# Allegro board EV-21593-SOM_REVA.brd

Outline 63.5 x 101.6 mm; copper layers: TOP, L2_PWR, L3_GND, L4_SIG, L5_SIG, L6_GND, L7_PWR, BOTTOM. Coordinates in mm from the lower left corner of the outline.
Outline path: 0,101.6 0,0 63.5,0 63.5,101.6 0,101.6

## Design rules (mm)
constraint set DEFAULT: min track width 0.076
net group 90_OHM_E: nets $9N2153 $9N2154
net group ADD_CNTRL_E: nets DMC0_A00 DMC0_A01 DMC0_A02 DMC0_A03 DMC0_A04 DMC0_A05 DMC0_A06 DMC0_A07 DMC0_A08 DMC0_A09 DMC0_A10 DMC0_A11 DMC0_A12 DMC0_A13 DMC0_A14 DMC0_A15 DMC0_BA0 DMC0_BA1 DMC0_BA2 DMC0_CKE DMC0_ODT ~DMC0_CAS ~DMC0_CS0 ~DMC0_RAS ~DMC0_WE
net group CLOCK_E: nets $5N38 AUDIO_CLK DAI0_PIN01 DAI0_PIN02 DAI0_PIN04 PA_04/SPI2_CLK/OSPI_CLK/SMC0_D04 PC_07/LP1_CLK/OSPI_SEL4B/TM0_TMR9/SYS_FAULT SYS_CLKIN0 SYS_CLKOUT
net group DDR_LOWER_E: nets DMC0_DQ00 DMC0_DQ01 DMC0_DQ02 DMC0_DQ03 DMC0_DQ04 DMC0_DQ05 DMC0_DQ06 DMC0_DQ07 DMC0_LDM
net group DDR_UPPER_E: nets DMC0_DQ08 DMC0_DQ09 DMC0_DQ10 DMC0_DQ11 DMC0_DQ12 DMC0_DQ13 DMC0_DQ14 DMC0_DQ15 DMC0_UDM
net group PWR/GND_E: nets 1_8V 1_35V 1V2 2V7 3V 3V3OUT_FT232RQ $6N3598 $6N5877 $8N2576 $8N2617 $8N3809 $8N3812 $9N2124 $9N2155 $12N6006 $12N7788 $12N7803 $12N7837 $12N8016 $12N8049 $12N8051 $12N8425 $12N8479 $13N133 $13N256 $13N259 $13N306 $13N308 $13N309 $13N457 $13N525 $13N528 $13N593 $13N599 $13N626 CC1 CC2 DMC0_VREF GND INTVCC PG1 PG3 PG4 USB_SHELL USB_VBUS VBUS_TYPEC VDD_CONNECTOR VDD_EXT VDD_INPUT VDD_INT VDD_PLL VDD_VREF_EXT VTT

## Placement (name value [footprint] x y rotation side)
C1  .10  [CAPC0603X33N]  44.7 81.92 180 bottom
C2  .10  [CAPC2012X135N]  54.61 77.34 180 top
C3  .10  [CAPC2012X135N]  54.61 75.18 180 top
C4  .10  [CAPC2012X135N]  59.69 72.64 0 top
C5  .10  [CAPC2012X135N]  59.64 67.79 0 top
C6  .10  [CAPC2012X135N]  59.64 70.19 0 top
C7  .10  [CAPC1005X55N]  55.24 68.58 270 top
C8  .10  [CAPC1608X55N]  52.44 67.99 270 top
C9  .10  [CAPC1005X56N]  49.91 72.01 0 top
C10  .10  [CAPC1005X55N]  47.42 56.54 0 bottom
C11  .10  [CAPC1005X56N]  32.22 70.74 90 top
C12  .10  [CAPC1005X56N]  41.62 77.74 0 top
C13  .10  [CAPC1005X56N]  41.62 76.14 0 top
C14  .10  [CAPC1005X56N]  41.62 74.54 0 top
C15  .10  [CAPC1005X56N]  41.62 71.34 0 top
C16  .10  [CAPC1005X56N]  41.62 72.94 0 top
C17  .10  [CAPC3225X270N]  54.23 80.9 90 top
C18  .10  [CAPC3225X270N]  47.62 66.04 270 bottom
C19  .10  [CAPC3216X180N]  40.64 85.09 270 bottom
C20  .10  [CAPC3216X180N]  50.67 66.04 270 bottom
C21  .10  [CAPC1005X55N]  32.22 81.94 90 top
C22  .10  [CAPC1005X55N]  37.82 81.94 90 top
C23  .10  [CAPC1005X55N]  29.82 81.94 90 top
C24  .10  [CAPC1005X55N]  28.22 70.74 270 top
C25  .10  [CAPC1005X55N]  30.62 70.74 270 top
C26  .10  [CAPC1005X55N]  37.82 70.74 270 top
C27  .10  [CAPC1005X55N]  28.22 81.94 90 top
C28  .10  [CAPC1005X56N]  48.64 58.17 90 top
C29  .10  [CAPC1608X90N]  46.99 58.42 90 top
C30  .10  [CAPC1005X56N]  48.64 53.72 90 top
C31  .10  [CAPC1608X90N]  46.99 54.1 90 top
C32  .10  [CAPC1005X55N]  29.92 53.64 0 bottom
C33  .10  [CAPC1005X55N]  19.62 56.14 90 bottom
C34  .10  [CAPC0603X33N]  35.18 85.85 270 bottom
C35  .10  [CAPC0603X33N]  42.55 65.66 270 bottom
C36  .10  [CAPC1005X56N]  21.84 46.61 180 top
C37  .10  [CAPC1005X56N]  47.42 48.54 0 top
C38  .10  [CAPC1005X56N]  44.22 50.14 0 top
C39  .10  [CAPC2012X135N]  47.22 42.14 270 bottom
C40  .10  [CAPC2012X135N]  18.62 42.14 270 bottom
C41  .10  [CAPC2012X135N]  17.82 52.94 180 bottom
C42  .10  [CAPC2012X135N]  17.82 50.54 180 bottom
C43  .10  [CAPC2012X135N]  18.62 45.94 90 bottom
C44  .10  [CAPC2012X135N]  50.42 47.34 270 bottom
C45  .10  [CAPC1005X55N]  22.62 42.14 270 bottom
C46  .10  [CAPC1005X55N]  44.22 45.34 0 top
C47  .10  [CAPC1005X55N]  47.42 50.14 0 top
C48  .10  [CAPC1005X55N]  47.42 46.94 0 top
C49  .10  [CAPC1005X55N]  47.42 51.74 0 top
C50  .10  [CAPC1005X55N]  44.22 48.54 0 top
C51  .10  [CAPC1005X55N]  47.42 45.34 0 top
C52  .10  [CAPC1005X55N]  21.82 55.34 180 top
C53  .10  [CAPC1005X55N]  21.82 54.14 180 top
C54  .10  [CAPC1005X55N]  21.82 52.94 180 top
C55  .10  [CAPC1005X55N]  21.82 49.14 180 top
C56  .10  [CAPC1005X55N]  38.22 53.34 0 bottom
C57  .10  [CAPC1005X50N]  21.82 58.14 180 top
C58  .10  [CAPC1005X50N]  27.82 55.74 180 bottom
C59  .10  [CAPC1005X50N]  35.42 53.34 180 bottom
C60  .10  [CAPC1005X50N]  38.62 58.34 90 bottom
C61  .10  [CAPC1005X50N]  27.42 53.34 180 bottom
C62  .10  [CAPC1005X50N]  21.82 56.74 180 top
C63  .10  [CAPC1005X50N]  21.82 61.34 180 top
C64  .10  [CAPC1005X50N]  21.82 56.74 180 bottom
C65  .10  [CAPC1005X50N]  21.82 52.94 180 bottom
C66  .10  [CAPC1005X50N]  21.82 59.74 180 bottom
C67  .10  [CAPC1005X50N]  21.82 47.94 180 bottom
C68  .10  [CAPC1005X50N]  21.82 61.34 180 bottom
C69  .10  [CAPC1005X50N]  21.82 49.14 180 bottom
C70  .10  [CAPC1005X50N]  21.82 50.54 180 top
C71  .10  [CAPC1005X50N]  21.82 58.14 180 bottom
C72  .10  [CAPC1005X50N]  28.02 49.44 0 bottom
C73  .10  [CAPC1005X50N]  30.62 42.14 270 bottom
C74  .10  [CAPC1005X50N]  25.82 42.14 270 bottom
C75  .10  [CAPC1005X50N]  21.02 42.14 270 bottom
C76  .10  [CAPC1005X50N]  43.42 42.14 270 bottom
C77  .10  [CAPC1005X50N]  45.02 42.14 270 bottom
C78  .10  [CAPC1005X50N]  42.02 42.14 270 bottom
C79  .10  [CAPC1005X50N]  39.02 50.94 0 bottom
C80  .10  [CAPC1005X50N]  29.02 42.14 270 bottom
C81  .10  [CAPC1005X50N]  24.22 42.14 270 bottom
C82  .10  [CAPC1005X50N]  29.02 42.14 270 top
C83  .10  [CAPC1005X50N]  32.22 42.14 270 top
C84  .10  [CAPC1005X50N]  35.42 42.14 270 bottom
C85  .10  [CAPC1005X50N]  27.42 42.14 270 bottom
C86  .10  [CAPC1005X50N]  32.22 42.14 270 bottom
C87  .10  [CAPC1005X50N]  33.82 42.14 270 bottom
C88  .10  [CAPC1005X50N]  33.82 42.14 270 top
C89  .10  [CAPC1005X55N]  44.22 58.14 0 bottom
C90  .10  [CAPC1005X55N]  44.22 64.54 0 bottom
C91  .10  [CAPC1005X55N]  35.42 55.34 270 bottom
C92  .10  [CAPC1005X55N]  30.62 55.34 270 bottom
C93  .10  [CAPC1005X55N]  44.22 61.34 0 top
C94  .10  [CAPC1005X55N]  44.22 59.74 0 top
C95  .10  [CAPC1005X55N]  35.42 64.34 90 bottom
C96  .10  [CAPC1005X55N]  44.22 62.94 0 top
C97  .10  [CAPC1005X55N]  33.42 56.54 180 bottom
C98  .10  [CAPC1005X50N]  32.22 64.34 90 top
C99  .10  [CAPC1005X50N]  47.42 61.34 0 bottom
C100  .10  [CAPC1005X50N]  47.42 62.94 0 top
C101  .10  [CAPC1005X50N]  33.82 64.34 90 top
C102  .10  [CAPC1005X50N]  38.62 64.34 90 bottom
C103  .10  [CAPC1005X50N]  35.42 64.34 90 top
C104  .10  [CAPC1005X50N]  44.22 58.14 0 top
C105  .10  [CAPC1005X50N]  37.02 64.34 90 top
C106  .10  [CAPC1005X50N]  38.62 64.34 90 top
C107  .10  [CAPC1005X50N]  47.42 62.94 0 bottom
C108  .10  [CAPC1005X50N]  47.42 61.34 0 top
C109  .10  [CAPC1005X50N]  32.22 64.34 90 bottom
C110  .10  [CAPC1005X50N]  33.82 64.34 90 bottom
C111  .10  [CAPC1005X55N]  21.82 64.14 90 bottom
C112  .10  [CAPC1005X55N]  44.22 59.74 0 bottom
C113  .10  [CAPC1005X55N]  21.82 54.14 180 bottom
C114  .10  [CAPC1005X55N]  21.82 55.34 180 bottom
C115  .10  [CAPC1005X55N]  21.82 51.74 180 bottom
C116  .10  [CAPC1005X55N]  21.82 50.54 180 bottom
C117  .10  [CAPC1005X56N]  44.22 61.34 0 bottom
C118  .10  [CAPC1005X56N]  44.22 62.94 0 bottom
C119  .10  [CAPC1005X56N]  37.02 64.34 90 bottom
C120  .10  [CAPC0603X33N]  33.82 50.94 90 bottom
C121  .10  [CAPC0603X33N]  31.42 50.94 90 bottom
C122  .10  [CAPC0603X33N]  30.02 52.54 0 bottom
C123  .10  [CAPC0603X33N]  32.22 50.94 90 bottom
C124  .10  [CAPC0603X33N]  43.42 42.14 270 top
C125  .10  [CAPC0603X33N]  35.42 42.14 270 top
C126  .10  [CAPC0603X33N]  42.02 42.14 270 top
C127  .10  [CAPC0603X33N]  45.02 42.14 270 top
C128  .10  [CAPC0603X33N]  21.02 42.14 270 top
C129  .10  [CAPC0603X33N]  25.82 42.14 270 top
C130  .10  [CAPC0603X33N]  34.62 50.94 90 bottom
C131  .10  [CAPC0603X33N]  30.62 50.94 90 bottom
C132  .10  [CAPC0603X33N]  47.42 51.74 0 bottom
C133  .10  [CAPC0603X33N]  44.22 45.34 0 bottom
C134  .10  [CAPC0603X33N]  47.42 46.94 0 bottom
C135  .10  [CAPC0603X33N]  47.42 50.14 0 bottom
C136  .10  [CAPC0603X33N]  44.22 50.14 0 bottom
C137  .10  [CAPC0603X33N]  21.84 45.34 180 bottom
C138  .10  [CAPC0603X33N]  44.22 46.94 0 bottom
C139  .10  [CAPC0603X33N]  47.42 45.34 0 bottom
C140  .10  [CAPC0603X33N]  21.84 46.61 180 bottom
C141  .10  [CAPC1005X55N]  9.53 56.52 180 top
C142  .10  [CAPC1005X55N]  9.53 45.09 180 top
C143  .10  [CAPC1005X55N]  46.99 32.38 270 bottom
C144  .10  [CAPC1005X55N]  46.99 34.92 90 bottom
C145  .10  [CAPC1005X55N]  43.18 34.92 270 bottom
C146  .10  [CAPC1005X56N]  17.72 63.88 90 bottom
C147  .10  [CAPC1005X56N]  58.42 32.38 180 top
C148  .10  [CAPC1005X56N]  58.42 41.27 180 top
C149  .10  [CAPC1005X56N]  58.42 27.3 180 top
C150  .10  [CAPC2012X135N]  53.85 59.18 270 top
C151  .10  [CAPC1005X55N]  45.47 12.06 90 top
C152  .10  [CAPC2012X140N]  28.19 26.16 180 bottom
C153  .10  [CAPC3216X180N]  50.29 15.62 90 top
C154  .10  [CAPC3216X180N]  60.96 63.5 90 top
C155  .10  [CAPC3225X280N]  11.43 22.73 90 top
C156  .10  [CAPC0603X33N]  47.12 15.88 90 top
C157  .10  [CAPC0603X33N]  42.93 15.49 90 top
C158  .10  [CAPC3216X127N]  21.34 16.89 270 top
C159  .10  [CAPC3225X280N]  24.38 16.89 270 top
C160  .10  [CAPC3216X127N]  14.22 16.89 270 top
C161  .10  [CAPC3225X280N]  11.3 16.89 270 top
C162  .10  [CAPC1608X87N]  17.78 19.05 180 top
C163  .10  [CAPC1005X55N]  17.78 10.79 90 top
C164  .10  [CAPC3225X280N]  22.23 21.72 0 top
C165  .10  [CAPC3225X280N]  22.23 25.02 0 top
C166  .10  [CAPC3225X280N]  22.23 28.32 0 top
C167  .10  [CAPC3216X127N]  22.73 12.06 90 top
C168  .10  [CAPC1005X55N]  16.51 10.79 270 top
C169  .10  [CAPC1005X50N]  29.34 18.67 90 top
C170  .10  [CAPC1005X50N]  34.92 18.41 270 top
C171  .10  [CAPC3216X180N]  36.83 19.18 270 top
C172  .10  [CAPC3216X180N]  27.43 19.43 90 top
C173  .10  [CAPC1005X55N]  27.81 13.08 90 top
C174  .10  [CAPC1608X90N]  31.12 12.57 90 top
C175  .10  [CAPC3216X180N]  40.64 15.62 90 top
C176  .10  [CAPC1005X56N]  48.01 9.91 90 top
C177  .10  [CAPC1005X55N]  33.15 28.45 90 top
C178  .10  [CAPC1608X90N]  33.02 12.57 90 top
C179  .10  [CAPC3225X280N]  27.56 23.49 180 top
C180  .10  [CAPC3225X280N]  27.56 26.8 180 top
C181  .10  [CAPC3225X280N]  36.7 23.49 0 top
C182  .10  [CAPC3225X280N]  27.56 23.49 180 bottom
C183  .10  [CAPC3225X280N]  36.7 23.49 0 bottom
C184  .10  [CAPC3225X280N]  36.7 26.8 0 top
C185  .10  [CAPC1005X50N]  29.21 13.08 90 top
C186  .10  [CAPC1005X56N]  22.23 38.73 90 bottom
C187  .10  [CAPC1005X56N]  17.15 34.92 270 bottom
C188  .10  [CAPC1005X56N]  17.15 38.73 270 bottom
C189  .10  [CAPC1005X56N]  17.15 31.12 270 bottom
C190  .10  [CAPC1005X56N]  16 79.25 90 bottom
C191  .10  [CAPC1005X55N]  19.69 93.34 270 bottom
C192  .10  [CAPC1005X55N]  7.62 98.43 90 bottom
C193  .10  [CAPC1005X55N]  13.46 87.12 0 bottom
C194  .10  [CAPC1608X90N]  10.29 87.12 180 bottom
C195  .10  [CAPC1005X55N]  19.81 82.93 270 bottom
C196  .10  [CAPC1005X55N]  18.54 82.93 270 bottom
C197  .10  [CAPC0603X33N]  47.42 48.54 0 bottom
C198  .10  [CAPC0603X33N]  44.22 48.54 0 bottom
C199  .10  [CAPC0603X33N]  21.82 45.34 180 top
C200  .10  [CAPC0603X33N]  30.62 42.14 270 top
C201  .10  [CAPC0603X33N]  44.7 72.01 180 bottom
C202  .10  [CAPC0603X33N]  44.7 78.49 180 bottom
C203  .10  [CAPC0603X33N]  44.7 75.31 180 bottom
C204  .10  [CAPC0603X33N]  38.8 85.85 270 bottom
C205  .10  [CAPC0603X33N]  41.53 65.66 270 bottom
C206  .10  [CAPC0603X33N]  33.27 87.76 180 bottom
C207  .10  [CAPC0603X33N]  33.27 86.74 180 bottom
C208  .10  [CAPC3216X180N]  26.67 91.44 180 top
C209  .10  [CAPC2012X145N]  44.58 98.43 270 bottom
C210  .10  [CAPC2012X145N]  47.24 98.43 270 bottom
C211  .10  [CAPC2012X145N]  42.04 98.43 270 bottom
C212  .10  [CAPC1005X55N]  55.24 95.25 270 top
C213  .10  [CAPC2012X145N]  36.83 92.08 270 top
C214  .10  [CAPC3216X180N]  50.16 26.67 0 top
C215  .10  [CAPC3216X180N]  50.16 24.13 0 top
C216  .10  [CAPC3216X180N]  50.16 21.59 0 top
C217  .10  [CAPC1005X55N]  37.21 15.49 90 top
C218  .10  [CAPC1608X90N]  37.46 10.35 270 top
C219  .10  [CAPC1005X56N]  56.52 8.26 90 top
D1  -  [SOT95P280X145-6N]  17.78 92.71 0 top
D2  -  [DFN50P250X100X55-10N]  13.97 93.34 180 top
D3  -  [SOT65P210X110-5N]  31.75 91.44 0 top
D4  .10  [DIOM4326X210N_KA]  40 97.16 90 top
D5  .10  [DIOM1610X55N_KA]  27.56 88.9 180 top
D6  .10  [DIOM1610X55N_KA]  52.07 94.62 270 top
FER1  .10  [INDC3216X130N]  17.15 92.71 270 bottom
FER2  .10  [INDC3216X130N]  10.79 92.71 270 bottom
FER3  -  [FILT_NFE61P]  54.61 55.63 180 top
FER4  -  [FILT_NFE61P]  54.61 52.7 180 top
J1  -  [SAMTEC_LSS-150-01-L-DV-A-K]  58.48 28.39 270 bottom
J2  -  [SAMTEC_LSS-150-01-L-DV-A-K]  31.48 4.88 180 bottom
J3  -  [SAMTEC_LSS-150-01-L-DV-A-K]  4.98 28.39 90 bottom
JP1  -  [SAMTEC_TSM-103-01-T-SV]  5.46 19.69 0 top
L1  .10  [IND_LQH32PN]  16.42 56.44 0 bottom
L3  .10  [IND_XFL5015]  44.96 19.56 90 top
L4  .10  [IND_XAL5030-102]  16.51 22.86 90 top
L5  .10  [IND_SRP4020TA]  32.13 21.59 90 top
LED1  .10  [LEDC1608X80N_KA]  21.59 69.85 180 top
LED2  .10  [LEDC1608X80N_KA]  2.54 60.32 270 top
LED3  .10  [LEDC1608X80N_KA]  8.26 60.32 270 top
LED4  .10  [LEDC1608X80N_KA]  6.35 60.32 270 top
LED5  .10  [LEDC1608X80N_KA]  4.45 60.32 270 top
LED6  .10  [LEDC1608X80N_KA]  53.34 31.75 0 top
LED7  .10  [LEDC1608X80N_KA]  6.35 97.79 90 top
LED8  .10  [LEDC1608X80N_KA]  4.45 97.79 90 top
P1  -  [SAMTEC_SHF-105-01-L-D-TH]  3.81 53.98 270 top
P2  -  [HIROSE_ZX62D-AB-5P8]  13.97 101.6 180 top
P3  -  [MOLEX_105450-0101]  30.48 101.6 180 top
R1  .10  [RESC1005X40N]  44.22 54.94 0 bottom
R2  .10  [RESC1005X40N]  44.22 56.54 180 bottom
R3  .10  [RESC1005X40N]  36.22 81.94 270 top
R4  .10  [RESC1005X40N]  41.62 79.34 0 top
R5  .10  [RESC1005X40N]  34.62 81.94 90 top
R6  .10  [RESC1005X40N]  39.22 70.74 90 top
R7  .10  [RESC1005X40N]  41.62 80.94 0 top
R8  .10  [RESC1005X40N]  49.91 73.28 180 top
R9  .10  [RESC1005X40N]  21.82 67.94 0 top
R10  .10  [RESC1005X40N]  21.82 66.34 0 top
R11  .10  [RESC1005X40N]  21.82 62.94 0 top
R12  .10  [RESC1005X40N]  21.82 64.54 180 top
R13  .10  [RESC1005X40N]  44.22 51.74 0 top
R14  .10  [RESC1005X40N]  59.69 52.7 90 top
R15  .10  [RESC1005X40N]  19.62 58.34 90 bottom
R16  .10  [RESC1005X40N]  33.42 77.34 0 bottom
R17  .10  [RESC1005X40N]  48.89 90.17 90 top
R18  .10  [RESC1005X40N]  41.27 32.38 270 bottom
R19  .10  [RESC1005X40N]  43.18 32.38 90 bottom
R20  .10  [RESC1005X40N]  8.89 79.69 0 bottom
R21  .10  [RESC1005X40N]  2.54 69.85 180 bottom
R22  .10  [RESC1005X40N]  2.86 79.69 180 bottom
R23  .10  [RESC1005X40N]  44.45 38.1 90 top
R24  .10  [RESC1005X40N]  49.53 33.02 0 top
R25  .10  [RESC1005X40N]  43.18 38.1 270 bottom
R26  .10  [RESC1005X40N]  61.47 52.7 270 top
R27  .10  [RESC1005X40N]  48.89 34.92 270 bottom
R28  .10  [RESC1005X40N]  48.89 32.38 90 bottom
R29  .10  [RESC1005X50N]  15.62 16.13 270 bottom
R30  .10  [RESC1005X40N]  46.99 38.1 90 top
R31  .10  [RESC1005X40N]  44.77 31.75 180 bottom
R32  .10  [RESC1005X40N]  19.05 53.34 180 top
R33  .10  [RESC1005X40N]  19.05 52.07 0 top
R34  .10  [RESC1005X37N]  17.15 52.7 270 top
R35  .10  [RESC1005X40N]  17.15 55.24 90 top
R36  .10  [RESC1005X40N]  2.54 63.5 90 top
R37  .10  [RESC1005X40N]  4.45 63.5 90 top
R38  .10  [RESC1005X40N]  6.35 63.5 90 top
R39  .10  [RESC1005X40N]  8.26 63.5 90 top
R40  .10  [RESC1005X40N]  16.13 70.87 270 top
R41  .10  [RESC1005X40N]  14.22 68.33 270 top
R42  .10  [RESC1005X40N]  14.22 70.87 270 top
R43  .10  [RESC1005X40N]  16.13 68.33 270 top
R44  .10  [RESC1005X40N]  12.32 68.33 270 top
R45  .10  [RESC1005X40N]  12.32 70.87 270 top
R46  .10  [RESC1005X40N]  52.07 29.84 180 top
R47  .10  [RESC1005X40N]  59.05 21.59 90 top
R48  .10  [RESC1005X40N]  57.79 21.59 90 top
R49  .10  [RESC1005X40N]  54.61 29.84 0 top
R50  .10  [RESC1005X40N]  54.61 39.37 0 top
R51  .10  [RESC1005X40N]  54.61 38.1 0 top
R52  .10  [RESC1005X40N]  46.74 12.06 270 top
R53  .10  [RESC3216X70N]  14.6 27.3 180 top
R54  .10  [RESC1005X40N]  20.32 10.79 270 top
R55  .10  [RESC1005X50N]  19.05 10.79 90 top
R56  .10  [RESC1005X40N]  20.83 13.33 270 top
R57  .10  [RESC1005X40N]  13.97 13.33 90 top
R58  .10  [RESC1005X40N]  15.24 13.33 90 top
R59  .10  [RESC1005X50N]  15.24 10.79 270 top
R60  .10  [RESC1005X40N]  29.21 10.67 270 top
R61  .10  [RESC1005X50N]  28.32 14.99 180 top
R62  .10  [RESC1005X50N]  42.93 12.06 270 top
R63  .10  [RESC1005X50N]  44.2 12.06 90 top
R64  .10  [RESC1005X50N]  34.67 13.21 90 top
R65  .10  [RESC1005X50N]  34.67 10.67 90 top
R66  .10  [RESC1005X50N]  35.94 13.21 270 top
R67  .10  [RESC1005X40N]  35.42 38.94 270 bottom
R68  .10  [RESC1005X40N]  33.82 38.94 270 bottom
R69  .10  [RESC1005X40N]  35.42 38.94 270 top
R70  .10  [RESC1005X40N]  33.82 38.94 270 top
R71  .10  [RESC1005X40N]  27.3 38.73 270 bottom
R72  .10  [RESC1005X40N]  23.49 31.75 90 bottom
R73  .10  [RESC1005X40N]  26.03 38.73 90 bottom
R74  .10  [RESC1005X40N]  12.06 34.92 270 bottom
R75  .10  [RESC1005X40N]  12.7 31.12 90 bottom
R76  .10  [RESC1005X40N]  10.79 34.92 90 bottom
R77  .10  [RESC1005X40N]  23.49 34.29 270 bottom
R78  .10  [RESC1005X40N]  23.49 38.73 90 bottom
R79  .10  [RESC1005X40N]  26.03 31.75 270 bottom
R80  .10  [RESC1005X40N]  24.77 31.75 270 bottom
R81  .10  [RESC1005X40N]  13.97 31.12 270 bottom
R82  .10  [RESC1608X50N]  7.62 95.76 270 bottom
R83  .10  [RESC1005X40N]  6.35 94.62 270 top
R84  .10  [RESC1005X40N]  4.45 94.62 270 top
R85  .10  [RESC1005X40N]  11.68 89.03 180 bottom
R86  .10  [RESC1005X40N]  12.19 78.36 270 bottom
R87  .10  [RESC1005X40N]  12.19 75.82 90 bottom
R88  .10  [RESC1005X40N]  16 75.18 270 bottom
R89  .10  [RESC1005X40N]  14.73 79.25 90 bottom
R90  .10  [RESC1005X40N]  14.73 75.18 90 bottom
R91  .10  [RESC1005X40N]  18.54 76.45 270 bottom
R92  .10  [RESC1005X40N]  9.53 47.62 180 top
R93  .10  [RESC1005X40N]  9.53 46.35 0 top
R94  .10  [RESC1005X40N]  9.53 48.89 0 top
R95  .10  [RESC1005X40N]  4.45 9.53 90 top
R96  .10  [RESC1005X40N]  3.18 9.53 90 top
R97  .10  [RESC1005X40N]  6.99 9.53 90 top
R98  .10  [RESC1005X40N]  1.91 9.53 90 top
R99  .10  [RESC1005X40N]  5.71 9.53 90 top
R100  .10  [RESC1005X40N]  56.52 68.58 90 top
R101  .10  [RESC1005X40N]  53.98 68.58 270 top
R102  .10  [RESC1005X40N]  47.62 90.17 90 top
R103  .10  [RESC1005X40N]  48.89 90.17 270 bottom
R104  .10  [RESC1005X40N]  47.62 90.17 270 bottom
R105  .10  [RESC1005X40N]  41.78 90.17 270 top
R106  .10  [RESC1005X40N]  47.62 99.06 90 top
R107  .10  [RESC1005X40N]  55.24 98.93 270 top
R108  .10  [RESC1005X40N]  56.52 95.25 270 top
R109  .10  [RESC1005X40N]  39.62 92.84 0 top
R110  .10  [RESC2012X70N]  36.83 95.89 270 top
R111  .10  [RESC1005X40N]  53.98 95.25 270 top
R112  .10  [RESC1005X40N]  44.32 90.17 270 top
R113  .10  [RESC1005X40N]  45.59 90.17 270 top
R114  .10  [RESC1005X40N]  50.16 90.17 270 top
R115  .10  [RESC1005X40N]  43.05 90.17 270 top
R116  .10  [RESC1005X50N]  35.94 10.67 270 top
R117  .10  [RESC1005X40N]  37.21 13.21 90 top
R118  .10  [RESC1005X40N]  48.01 12.06 90 top
R119  .10  [RESC1005X40N]  23.82 53.74 270 bottom
R120  .10  [RESC1005X40N]  25.02 53.74 270 bottom
R121  .10  [RESC1005X40N]  12.7 13.33 270 top
R122  .10  [RESC1005X40N]  12.7 10.79 270 top
R123  .10  [RESC1005X40N]  11.43 10.79 270 top
R124  .10  [RESC1005X40N]  11.43 13.33 270 top
R125  .10  [RESC1005X40N]  53.72 5.97 180 top
R126  .10  [RESC1005X40N]  53.72 10.54 180 top
R127  .10  [RESC1608X55N]  13.97 14.6 90 bottom
RN1  -  [RESCAXE50P100X200X45-8N]  42.62 76.94 0 bottom
RN2  -  [RESCAXE50P100X200X45-8N]  42.62 73.74 0 bottom
RN3  -  [RESCAXE50P100X200X45-8N]  42.62 80.14 0 bottom
RN4  -  [RESCAXE50P100X200X45-8N]  37.02 84.94 90 bottom
RN5  -  [RESCAXE50P100X200X45-8N]  37.02 68.14 270 bottom
RN6  -  [RESCAXE50P100X200X45-8N]  33.82 68.14 270 bottom
RN7  -  [RESCAXE50P100X200X45-8N]  33.31 84.94 90 bottom
SW1  -  [SW_RDTAR10S1R]  5.71 73.03 270 top
SW2  -  [SW_KMR223GLFG]  58.42 34.92 0 top
TP1  -  [TP_5001_DBL]  45.09 26.03 180 top
TP2  -  [TP_5001_DBL]  60.96 59.05 0 top
TP3  -  [TP_5001_DBL]  10.79 27.3 0 top
TP4  -  [TP_5001_DBL]  18.41 27.3 0 top
U1  -  [BGA400C80P20X20_1700X1700X150]  33.02 53.34 0 top
U2  -  [SOIC127P1030X265-16N]  24.77 35.56 0 top
U3  -  [SOT95P280X100-5N]  57.4 58.93 0 top
U4  -  [SOT143X100N]  58.42 24.77 0 top
U5  -  [QFN50P300X300X100-19N]  32.13 16.64 180 top
U6  -  [SOT65P210X110-5N]  15.88 31.12 0 top
U7  -  [SOT65P210X110-5N]  15.88 34.92 0 top
U8  -  [SOT65P210X110-5N]  15.88 38.73 0 top
U9  -  [QFN50P400X400X90-25N]  45.09 33.66 0 top
U10  -  [QFN50P500X500X100-33V18N]  15.88 86.36 180 top
U11  -  [SOP65P640X120-14N]  15.37 77.09 0 top
U12  -  [DFN50P300X300X100-11NA]  55.04 71.99 90 top
U13  -  [BGA96C80P9X16_900X1400X110]  33.02 76.34 90 top
U14  -  [QFN50P200X200X83-13N]  45.09 14.92 180 top
U15  -  [QFN50P400X300X100-21N_CORNERS]  17.78 15.24 180 top
U16  -  [QFN65P600X600X100-29VNA]  14.86 62.61 180 top
U17  -  [SOT95P280X145-5N]  58.42 29.84 0 top
U18  -  [SOT95P280X145-5N]  58.42 38.73 0 top
U19  -  [POWERFLAT_3P3X3P3]  44.45 98.43 180 top
U20  -  [POWERFLAT_3P3X3P3]  52.07 98.43 180 top
U21  -  [QFN50P400X400X100-25NB]  46.35 93.98 0 top
U22  -  [SOT95P280X145-5N]  53.72 8.26 0 top
Y1  .10  [XTAL_CSM-7XDU]  13.33 50.8 270 top
Y2  .10  [XTAL_CSM-7XDU]  38.73 36.2 90 top
ZF1  -  [FIDUCIAL-GT]  59.69 92.08 0 top
ZF2  -  [FIDUCIAL-GT]  53.34 3.18 0 top
ZF3  -  [FIDUCIAL-GT]  10.16 3.18 0 top
ZF4  -  [FIDUCIAL-GT]  59.69 92.08 180 bottom
ZF5  -  [FIDUCIAL-GT]  53.34 3.18 180 bottom
ZF6  -  [FIDUCIAL-GT]  10.16 3.18 180 bottom
ZH1  -  [MTHOLE2]  59.69 85.09 0 top
ZH2  -  [MTHOLE2]  3.81 85.09 0 top
ZH3  -  [MTHOLE2]  3.81 3.81 0 top
ZH4  -  [MTHOLE2]  59.69 3.81 0 top
ZH5  -  [MTHOLE2]  -6.35 -6.35 0 top
ZH6  -  [MTHOLE2]  69.85 -6.35 0 top
ZH7  -  [MTHOLE2]  69.85 107.95 0 top
ZH8  -  [MTHOLE2]  -6.35 107.95 0 top

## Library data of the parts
C1 C34 C35 C120-C140 C156 C157 C197-C207 = CAPC0603X33N
C2-C6 C39-C44 C150 = CAPC2012X135N
C7 C10 C21-C27 C32 C33 C45-C56 C89-C97 C111-C116 C141-C145 C151 C163 C168 C173 C177 C191-C193 C195 C196 C212 C217 = CAPC1005X55N
C8 = CAPC1608X55N
C9 C11-C16 C28 C30 C36-C38 C117-C119 C146-C149 C176 C186-C190 C219 = CAPC1005X56N
C17 C18 = CAPC3225X270N
C19 C20 C153 C154 C171 C172 C175 C208 C214-C216 = CAPC3216X180N
C29 C31 C174 C178 C194 C218 = CAPC1608X90N
C57-C88 C98-C110 C169 C170 C185 = CAPC1005X50N
C152 = CAPC2012X140N
C155 C159 C161 C164-C166 C179-C184 = CAPC3225X280N
C158 C160 C167 = CAPC3216X127N
C162 = CAPC1608X87N
C209-C211 C213 = CAPC2012X145N
D1 = SOT95P280X145-6N
D2 = DFN50P250X100X55-10N
D3 U6-U8 = SOT65P210X110-5N
D4 = DIOM4326X210N_KA
D5 D6 = DIOM1610X55N_KA
FER1 FER2 = INDC3216X130N
FER3 FER4 = FILT_NFE61P
J1-J3 = SAMTEC_LSS-150-01-L-DV-A-K
JP1 = SAMTEC_TSM-103-01-T-SV
L1 = IND_LQH32PN
L3 = IND_XFL5015
L4 = IND_XAL5030-102
L5 = IND_SRP4020TA
LED1-LED8 = LEDC1608X80N_KA
P1 = SAMTEC_SHF-105-01-L-D-TH
P2 = HIROSE_ZX62D-AB-5P8
P3 = MOLEX_105450-0101
R1-R28 R30-R33 R35-R52 R54 R56-R58 R60 R67-R81 R83-R109 R111-R115 R117-R126 = RESC1005X40N
R29 R55 R59 R61-R66 R116 = RESC1005X50N
R34 = RESC1005X37N
R53 = RESC3216X70N
R82 = RESC1608X50N
R110 = RESC2012X70N
R127 = RESC1608X55N
RN1-RN7 = RESCAXE50P100X200X45-8N
SW1 = SW_RDTAR10S1R
SW2 = SW_KMR223GLFG
TP1-TP4 = TP_5001_DBL
U1 = BGA400C80P20X20_1700X1700X150
U2 = SOIC127P1030X265-16N
U3 = SOT95P280X100-5N
U4 = SOT143X100N
U5 = QFN50P300X300X100-19N
U9 = QFN50P400X400X90-25N
U10 = QFN50P500X500X100-33V18N
U11 = SOP65P640X120-14N
U12 = DFN50P300X300X100-11NA
U13 = BGA96C80P9X16_900X1400X110
U14 = QFN50P200X200X83-13N
U15 = QFN50P400X300X100-21N_CORNERS
U16 = QFN65P600X600X100-29VNA
U17 U18 U22 = SOT95P280X145-5N
U19 U20 = POWERFLAT_3P3X3P3
U21 = QFN50P400X400X100-25NB
Y1 Y2 = XTAL_CSM-7XDU
ZF1-ZF6 = FIDUCIAL-GT
ZH1-ZH8 = MTHOLE2

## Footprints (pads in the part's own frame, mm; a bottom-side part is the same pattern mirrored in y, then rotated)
BGA96C80P9X16_900X1400X110
  round 0.381 smd: A1(-3.2,6) A2(-2.4,6) A3(-1.6,6) A7(1.6,6) A8(2.4,6) A9(3.2,6) B1(-3.2,5.2) B2(-2.4,5.2) B3(-1.6,5.2) B7(1.6,5.2) B8(2.4,5.2) B9(3.2,5.2) C1(-3.2,4.4) C2(-2.4,4.4) C3(-1.6,4.4) C7(1.6,4.4) C8(2.4,4.4) C9(3.2,4.4) D1(-3.2,3.6) D2(-2.4,3.6) D3(-1.6,3.6) D7(1.6,3.6) D8(2.4,3.6) D9(3.2,3.6) E1(-3.2,2.8) E2(-2.4,2.8) E3(-1.6,2.8) E7(1.6,2.8) E8(2.4,2.8) E9(3.2,2.8) F1(-3.2,2) F2(-2.4,2) F3(-1.6,2) F7(1.6,2) F8(2.4,2) F9(3.2,2) G1(-3.2,1.2) G2(-2.4,1.2) G3(-1.6,1.2) G7(1.6,1.2) G8(2.4,1.2) G9(3.2,1.2) H1(-3.2,0.4) H2(-2.4,0.4) H3(-1.6,0.4) H7(1.6,0.4) H8(2.4,0.4) H9(3.2,0.4) J1(-3.2,-0.4) J2(-2.4,-0.4) J3(-1.6,-0.4) J7(1.6,-0.4) J8(2.4,-0.4) J9(3.2,-0.4) K1(-3.2,-1.2) K2(-2.4,-1.2) K3(-1.6,-1.2) K7(1.6,-1.2) K8(2.4,-1.2) K9(3.2,-1.2) L1(-3.2,-2) L2(-2.4,-2) L3(-1.6,-2) L7(1.6,-2) L8(2.4,-2) L9(3.2,-2) M1(-3.2,-2.8) M2(-2.4,-2.8) M3(-1.6,-2.8) M7(1.6,-2.8) M8(2.4,-2.8) M9(3.2,-2.8) N1(-3.2,-3.6) N2(-2.4,-3.6) N3(-1.6,-3.6) N7(1.6,-3.6) N8(2.4,-3.6) N9(3.2,-3.6) P1(-3.2,-4.4) P2(-2.4,-4.4) P3(-1.6,-4.4) P7(1.6,-4.4) P8(2.4,-4.4) P9(3.2,-4.4) R1(-3.2,-5.2) R2(-2.4,-5.2) R3(-1.6,-5.2) R7(1.6,-5.2) R8(2.4,-5.2) R9(3.2,-5.2) T1(-3.2,-6) T2(-2.4,-6) T3(-1.6,-6) T7(1.6,-6) T8(2.4,-6) T9(3.2,-6)
BGA400C80P20X20_1700X1700X150
  round 0.356 smd: A1(-7.6,7.6) A2(-6.8,7.6) A3(-6,7.6) A4(-5.2,7.6) A5(-4.4,7.6) A6(-3.6,7.6) A7(-2.8,7.6) A8(-2,7.6) A9(-1.2,7.6) A10(-0.4,7.6) A11(0.4,7.6) A12(1.2,7.6) A13(2,7.6) A14(2.8,7.6) A15(3.6,7.6) A16(4.4,7.6) A17(5.2,7.6) A18(6,7.6) A19(6.8,7.6) A20(7.6,7.6) B1(-7.6,6.8) B2(-6.8,6.8) B3(-6,6.8) B4(-5.2,6.8) B5(-4.4,6.8) B6(-3.6,6.8) B7(-2.8,6.8) B8(-2,6.8) B9(-1.2,6.8) B10(-0.4,6.8) B11(0.4,6.8) B12(1.2,6.8) B13(2,6.8) B14(2.8,6.8) B15(3.6,6.8) B16(4.4,6.8) B17(5.2,6.8) B18(6,6.8) B19(6.8,6.8) B20(7.6,6.8) C1(-7.6,6) C2(-6.8,6) C3(-6,6) C4(-5.2,6) C5(-4.4,6) C6(-3.6,6) C7(-2.8,6) C8(-2,6) C9(-1.2,6) C10(-0.4,6) C11(0.4,6) C12(1.2,6) C13(2,6) C14(2.8,6) C15(3.6,6) C16(4.4,6) C17(5.2,6) C18(6,6) C19(6.8,6) C20(7.6,6) D1(-7.6,5.2) D2(-6.8,5.2) D3(-6,5.2) D4(-5.2,5.2) D5(-4.4,5.2) D6(-3.6,5.2) D7(-2.8,5.2) D8(-2,5.2) D9(-1.2,5.2) D10(-0.4,5.2) D11(0.4,5.2) D12(1.2,5.2) D13(2,5.2) D14(2.8,5.2) D15(3.6,5.2) D16(4.4,5.2) D17(5.2,5.2) D18(6,5.2) D19(6.8,5.2) D20(7.6,5.2) E1(-7.6,4.4) E2(-6.8,4.4) E3(-6,4.4) E4(-5.2,4.4) E5(-4.4,4.4) E6(-3.6,4.4) E7(-2.8,4.4) E8(-2,4.4) E9(-1.2,4.4) E10(-0.4,4.4) E11(0.4,4.4) E12(1.2,4.4) E13(2,4.4) E14(2.8,4.4) E15(3.6,4.4) E16(4.4,4.4) E17(5.2,4.4) E18(6,4.4) E19(6.8,4.4) E20(7.6,4.4) F1(-7.6,3.6) F2(-6.8,3.6) F3(-6,3.6) F4(-5.2,3.6) F5(-4.4,3.6) F6(-3.6,3.6) F7(-2.8,3.6) F8(-2,3.6) F9(-1.2,3.6) F10(-0.4,3.6) F11(0.4,3.6) F12(1.2,3.6) F13(2,3.6) F14(2.8,3.6) F15(3.6,3.6) F16(4.4,3.6) F17(5.2,3.6) F18(6,3.6) F19(6.8,3.6) F20(7.6,3.6) G1(-7.6,2.8) G2(-6.8,2.8) G3(-6,2.8) G4(-5.2,2.8) G5(-4.4,2.8) G6(-3.6,2.8) G7(-2.8,2.8) G8(-2,2.8) G9(-1.2,2.8) G10(-0.4,2.8) G11(0.4,2.8) G12(1.2,2.8) G13(2,2.8) G14(2.8,2.8) G15(3.6,2.8) G16(4.4,2.8) G17(5.2,2.8) G18(6,2.8) G19(6.8,2.8) G20(7.6,2.8) H1(-7.6,2) H2(-6.8,2) H3(-6,2) H4(-5.2,2) H5(-4.4,2) H6(-3.6,2) H7(-2.8,2) H8(-2,2) H9(-1.2,2) H10(-0.4,2) H11(0.4,2) H12(1.2,2) H13(2,2) H14(2.8,2) H15(3.6,2) H16(4.4,2) H17(5.2,2) H18(6,2) H19(6.8,2) H20(7.6,2) J1(-7.6,1.2) J2(-6.8,1.2) J3(-6,1.2) J4(-5.2,1.2) J5(-4.4,1.2) J6(-3.6,1.2) J7(-2.8,1.2) J8(-2,1.2) J9(-1.2,1.2) J10(-0.4,1.2) J11(0.4,1.2) J12(1.2,1.2) J13(2,1.2) J14(2.8,1.2) J15(3.6,1.2) J16(4.4,1.2) J17(5.2,1.2) J18(6,1.2) J19(6.8,1.2) J20(7.6,1.2) K1(-7.6,0.4) K2(-6.8,0.4) K3(-6,0.4) K4(-5.2,0.4) K5(-4.4,0.4) K6(-3.6,0.4) K7(-2.8,0.4) K8(-2,0.4) K9(-1.2,0.4) K10(-0.4,0.4) K11(0.4,0.4) K12(1.2,0.4) K13(2,0.4) K14(2.8,0.4) K15(3.6,0.4) K16(4.4,0.4) K17(5.2,0.4) K18(6,0.4) K19(6.8,0.4) K20(7.6,0.4) L1(-7.6,-0.4) L2(-6.8,-0.4) L3(-6,-0.4) L4(-5.2,-0.4) L5(-4.4,-0.4) L6(-3.6,-0.4) L7(-2.8,-0.4) L8(-2,-0.4) L9(-1.2,-0.4) L10(-0.4,-0.4) L11(0.4,-0.4) L12(1.2,-0.4) L13(2,-0.4) L14(2.8,-0.4) L15(3.6,-0.4) L16(4.4,-0.4) L17(5.2,-0.4) L18(6,-0.4) L19(6.8,-0.4) L20(7.6,-0.4) M1(-7.6,-1.2) M2(-6.8,-1.2) M3(-6,-1.2) M4(-5.2,-1.2) M5(-4.4,-1.2) M6(-3.6,-1.2) M7(-2.8,-1.2) M8(-2,-1.2) M9(-1.2,-1.2) M10(-0.4,-1.2) M11(0.4,-1.2) M12(1.2,-1.2) M13(2,-1.2) M14(2.8,-1.2) M15(3.6,-1.2) M16(4.4,-1.2) M17(5.2,-1.2) M18(6,-1.2) M19(6.8,-1.2) M20(7.6,-1.2) N1(-7.6,-2) N2(-6.8,-2) N3(-6,-2) N4(-5.2,-2) N5(-4.4,-2) N6(-3.6,-2) N7(-2.8,-2) N8(-2,-2) N9(-1.2,-2) N10(-0.4,-2) N11(0.4,-2) N12(1.2,-2) N13(2,-2) N14(2.8,-2) N15(3.6,-2) N16(4.4,-2) N17(5.2,-2) N18(6,-2) N19(6.8,-2) N20(7.6,-2) P1(-7.6,-2.8) P2(-6.8,-2.8) P3(-6,-2.8) P4(-5.2,-2.8) P5(-4.4,-2.8) P6(-3.6,-2.8) P7(-2.8,-2.8) P8(-2,-2.8) P9(-1.2,-2.8) P10(-0.4,-2.8) P11(0.4,-2.8) P12(1.2,-2.8) P13(2,-2.8) P14(2.8,-2.8) P15(3.6,-2.8) P16(4.4,-2.8) P17(5.2,-2.8) P18(6,-2.8) P19(6.8,-2.8) P20(7.6,-2.8) R1(-7.6,-3.6) R2(-6.8,-3.6) R3(-6,-3.6) R4(-5.2,-3.6) R5(-4.4,-3.6) R6(-3.6,-3.6) R7(-2.8,-3.6) R8(-2,-3.6) R9(-1.2,-3.6) R10(-0.4,-3.6) R11(0.4,-3.6) R12(1.2,-3.6) R13(2,-3.6) R14(2.8,-3.6) R15(3.6,-3.6) R16(4.4,-3.6) R17(5.2,-3.6) R18(6,-3.6) R19(6.8,-3.6) R20(7.6,-3.6) T1(-7.6,-4.4) T2(-6.8,-4.4) T3(-6,-4.4) T4(-5.2,-4.4) T5(-4.4,-4.4) T6(-3.6,-4.4) T7(-2.8,-4.4) T8(-2,-4.4) T9(-1.2,-4.4) T10(-0.4,-4.4) T11(0.4,-4.4) T12(1.2,-4.4) T13(2,-4.4) T14(2.8,-4.4) T15(3.6,-4.4) T16(4.4,-4.4) T17(5.2,-4.4) T18(6,-4.4) T19(6.8,-4.4) T20(7.6,-4.4) U1(-7.6,-5.2) U2(-6.8,-5.2) U3(-6,-5.2) U4(-5.2,-5.2) U5(-4.4,-5.2) U6(-3.6,-5.2) U7(-2.8,-5.2) U8(-2,-5.2) U9(-1.2,-5.2) U10(-0.4,-5.2) U11(0.4,-5.2) U12(1.2,-5.2) U13(2,-5.2) U14(2.8,-5.2) U15(3.6,-5.2) U16(4.4,-5.2) U17(5.2,-5.2) U18(6,-5.2) U19(6.8,-5.2) U20(7.6,-5.2) V1(-7.6,-6) V2(-6.8,-6) V3(-6,-6) V4(-5.2,-6) V5(-4.4,-6) V6(-3.6,-6) V7(-2.8,-6) V8(-2,-6) V9(-1.2,-6) V10(-0.4,-6) V11(0.4,-6) V12(1.2,-6) V13(2,-6) V14(2.8,-6) V15(3.6,-6) V16(4.4,-6) V17(5.2,-6) V18(6,-6) V19(6.8,-6) V20(7.6,-6) W1(-7.6,-6.8) W2(-6.8,-6.8) W3(-6,-6.8) W4(-5.2,-6.8) W5(-4.4,-6.8) W6(-3.6,-6.8) W7(-2.8,-6.8) W8(-2,-6.8) W9(-1.2,-6.8) W10(-0.4,-6.8) W11(0.4,-6.8) W12(1.2,-6.8) W13(2,-6.8) W14(2.8,-6.8) W15(3.6,-6.8) W16(4.4,-6.8) W17(5.2,-6.8) W18(6,-6.8) W19(6.8,-6.8) W20(7.6,-6.8) Y1(-7.6,-7.6) Y2(-6.8,-7.6) Y3(-6,-7.6) Y4(-5.2,-7.6) Y5(-4.4,-7.6) Y6(-3.6,-7.6) Y7(-2.8,-7.6) Y8(-2,-7.6) Y9(-1.2,-7.6) Y10(-0.4,-7.6) Y11(0.4,-7.6) Y12(1.2,-7.6) Y13(2,-7.6) Y14(2.8,-7.6) Y15(3.6,-7.6) Y16(4.4,-7.6) Y17(5.2,-7.6) Y18(6,-7.6) Y19(6.8,-7.6) Y20(7.6,-7.6)
CAPC0603X33N
  rect 0.457x0.406 smd: 1(-0.33,0) 2(0.33,0)
CAPC1005X50N
  rect 0.533x0.406 smd: 1(-0.45,0) 2(0.45,0)
CAPC1005X55N
  rect 0.61x0.61 smd: 1(-0.45,0) 2(0.45,0)
CAPC1005X56N
  rect 0.584x0.635 smd: 1(-0.48,0) 2(0.48,0)
CAPC1608X55N
  rect 0.889x0.94 smd: 1(-0.75,0) 2(0.75,0)
CAPC1608X87N
  rect 0.94x0.991 smd: 1(-0.8,0) 2(0.8,0)
CAPC1608X90N
  rect 0.94x0.991 smd: 1(-0.8,0) 2(0.8,0)
CAPC2012X135N
  rect 1.143x1.448 smd: 1(-0.9,0) 2(0.9,0)
CAPC2012X140N
  rect 1.143x1.448 smd: 1(-0.9,0) 2(0.9,0)
CAPC2012X145N
  rect 1.143x1.448 smd: 1(-0.9,0) 2(0.9,0)
CAPC3216X127N
  rect 1.143x1.803 smd: 1(-1.5,0) 2(1.5,0)
CAPC3216X180N
  rect 1.143x1.803 smd: 1(-1.5,0) 2(1.5,0)
CAPC3225X270N
  rect 1.143x2.692 smd: 1(-1.5,0) 2(1.5,0)
CAPC3225X280N
  rect 1.143x2.692 smd: 1(-1.5,0) 2(1.5,0)
DFN50P250X100X55-10N
  rect 0.254x0.508 smd: 1(-1,-0.4) 2(-0.5,-0.4) 4(0.5,-0.4) 5(1,-0.4) 6(1,0.4) 7(0.5,0.4) 9(-0.5,0.4) 10(-1,0.4)
  rect 0.406x0.508 smd: 3(0,-0.4) 8(0,0.4)
DFN50P300X300X100-11NA
  oval 0.279x0.838 smd: 1(-1,-1.5) 2(-0.5,-1.5) 3(0,-1.5) 4(0.5,-1.5) 5(1,-1.5) 6(1,1.5) 7(0.5,1.5) 8(0,1.5) 9(-0.5,1.5) 10(-1,1.5)
  rect 0.838x0.279 smd: 11(-1.486,0.254) 12(-1.486,-0.254) 13(1.486,0.254) 14(1.486,-0.254)
  rect 2.388x1.626 smd: 15(0,0)
DIOM1610X55N_KA
  rect 0.55x0.8 smd: A(0.625,0) K(-0.625,0)
DIOM4326X210N_KA
  rect 1.981x1.981 smd: A(1.981,0) K(-1.981,0)
FIDUCIAL-GT
  round 1.016 smd: 1(0,0)
FILT_NFE61P
  rect 1.27x2.032 smd: 1(-3.175,0) 3(3.175,0)
  rect 3.175x2.032 smd: 2(0,0)
HIROSE_ZX62D-AB-5P8
  rect 0.381x1.346 smd: 1(-1.3,4.825) 2(-0.65,4.825) 3(0,4.825) 4(0.65,4.825) 5(1.3,4.825)
  rect 2.616x1.346 hole 0.838x0.66: 6(-2.225,5.15) 7(2.225,5.15)
  rect 2.388x1.905 hole 1.499x0.838: 8(-4.088,2.15) 9(4.088,2.15)
  rect 1.803x1.905 smd: 10(-1.15,2.15) 11(1.15,2.15)
IND_LQH32PN
  rect 1.295x2.489 smd: 1(-1.3,0) 2(1.3,0)
IND_SRP4020TA
  rect 1.524x2.413 smd: 1(-1.85,0) 2(1.85,0)
IND_XAL5030-102
  rect 1.168x4.394 smd: 1(-1.65,0) 2(1.65,0)
IND_XFL5015
  rect 1.168x4.699 smd: 1(-1.651,0) 2(1.651,0)
INDC3216X130N
  rect 1.041x1.803 smd: 1(-1.5,0) 2(1.5,0)
LEDC1608X80N_KA
  rect 0.889x0.94 smd: A(0.8,0) K(-0.8,0)
MOLEX_105450-0101
  rect 0.305x0.711 smd: A1(-3,7.535) A2(-2.5,7.535) A3(-2,7.535) A4(-1.5,7.535) A5(-1,7.535) A6(-0.5,7.535) A7(0.5,7.535) A8(1,7.535) A9(1.5,7.535) A10(2,7.535) A11(2.5,7.535) A12(3,7.535) B2(2.25,6.23) B3(1.75,6.23) B4(1.25,6.23) B5(0.75,6.23) B6(0.25,6.23) B7(-0.25,6.23) B8(-0.75,6.23) B9(-1.25,6.23) B10(-1.75,6.23) B11(-2.25,6.23)
  rect 1.016x0.711 smd: B1(3.1,6.23) B12(-3.1,6.23)
  oval 1.118x2.108 hole 0.61x1.6: S1(-4.32,7.13) S2(4.32,7.13)
  oval 1.118x2.616 hole 0.61x2.108: S3(4.32,1.77) S4(-4.32,1.77)
MTHOLE2
  round 2.54 hole 3.175 unplated: (0,0)
POWERFLAT_3P3X3P3
  rect 0.991x0.432 smd: 1(-1.511,0.991) 2(-1.511,0.33) 3(-1.511,-0.33) 4(-1.511,-0.991) 5(1.511,-0.991) 6(1.511,-0.33) 7(1.511,0.33) 8(1.511,0.991)
  rect 1.829x3.404 smd: 9(0.457,0)
QFN50P200X200X83-13N
  rect 0.711x0.254 smd: 1(-0.9,0.75) 2(-0.9,0.25) 3(-0.9,-0.25) 4(-0.9,-0.75) 7(0.9,-0.75) 8(0.9,-0.25) 9(0.9,0.25) 10(0.9,0.75)
  rect 0.254x0.711 smd: 5(-0.25,-0.9) 6(0.25,-0.9) 11(0.25,0.9) 12(-0.25,0.9)
  rect 0.686x0.686 smd: 13(0,0)
QFN50P300X300X100-19N
  rect 0.686x0.254 smd: 1(-1.4,1) 2(-1.4,0.5) 3(-1.4,0) 4(-1.4,-0.5) 5(-1.4,-1) 10(1.4,-1) 11(1.4,-0.5) 12(1.4,0) 13(1.4,0.5) 14(1.4,1)
  rect 0.254x0.686 smd: 6(-0.75,-1.4) 7(-0.25,-1.4) 8(0.25,-1.4) 9(0.75,-1.4) 15(0.75,1.4) 16(0.25,1.4) 17(-0.25,1.4) 18(-0.75,1.4)
  rect 1.702x1.499 smd: 19(0,-0.1)
QFN50P400X300X100-21N_CORNERS
  rect 0.711x0.254 smd: 1(-1.4,1.25) 2(-1.4,0.75) 3(-1.4,0.25) 4(-1.4,-0.25) 5(-1.4,-0.75) 6(-1.4,-1.25) 11(1.4,-1.25) 12(1.4,-0.75) 13(1.4,-0.25) 14(1.4,0.25) 15(1.4,0.75) 16(1.4,1.25)
  rect 0.254x0.711 smd: 7(-0.75,-1.9) 8(-0.25,-1.9) 9(0.25,-1.9) 10(0.75,-1.9) 17(0.75,1.9) 18(0.25,1.9) 19(-0.25,1.9) 20(-0.75,1.9)
  rect 1.651x2.642 smd: 21(0,0)
  rect 0.381x0.381 smd: 22(1.312,1.813) 23(-1.312,1.813) 24(1.312,-1.813) 25(-1.312,-1.813)
QFN50P400X400X90-25N
  oval 0.889x0.279 smd: 1(-1.95,1.25) 2(-1.95,0.75) 3(-1.95,0.25) 4(-1.95,-0.25) 5(-1.95,-0.75) 6(-1.95,-1.25) 13(1.95,-1.25) 14(1.95,-0.75) 15(1.95,-0.25) 16(1.95,0.25) 17(1.95,0.75) 18(1.95,1.25)
  oval 0.279x0.889 smd: 7(-1.25,-1.95) 8(-0.75,-1.95) 9(-0.25,-1.95) 10(0.25,-1.95) 11(0.75,-1.95) 12(1.25,-1.95) 19(1.25,1.95) 20(0.75,1.95) 21(0.25,1.95) 22(-0.25,1.95) 23(-0.75,1.95) 24(-1.25,1.95)
  rect 2.54x2.54 smd: 25(0,0)
QFN50P400X400X100-25NB
  oval 0.584x0.254 smd: 1(-1.913,1.25) 2(-1.913,0.75) 3(-1.913,0.25) 4(-1.913,-0.25) 5(-1.913,-0.75) 6(-1.913,-1.25) 13(1.913,-1.25) 14(1.913,-0.75) 15(1.913,-0.25) 16(1.913,0.25) 17(1.913,0.75) 18(1.913,1.25)
  oval 0.254x0.584 smd: 7(-1.25,-1.913) 8(-0.75,-1.913) 9(-0.25,-1.913) 10(0.25,-1.913) 11(0.75,-1.913) 12(1.25,-1.913) 19(1.25,1.913) 20(0.75,1.913) 21(0.25,1.913) 22(-0.25,1.913) 23(-0.75,1.913) 24(-1.25,1.913)
  rect 2.692x2.692 smd: 25(0,0)
  round 0 smd: V1(0,0) V2(1.1,0) V3(0,1.1) V4(0,-1.1) V5(-1.1,0)
QFN50P500X500X100-33V18N
  round 0.1 smd: 1(-2.375,1.75) 8(-2.375,-1.75) 9(-1.75,-2.375) 16(1.75,-2.375) 17(2.375,-1.75) 24(2.375,1.75) 25(1.75,2.375) 32(-1.75,2.375)
  rect 0.838x0.305 smd: 2(-2.375,1.25) 3(-2.375,0.75) 4(-2.375,0.25) 5(-2.375,-0.25) 6(-2.375,-0.75) 7(-2.375,-1.25) 18(2.375,-1.25) 19(2.375,-0.75) 20(2.375,-0.25) 21(2.375,0.25) 22(2.375,0.75) 23(2.375,1.25)
  rect 0.305x0.838 smd: 10(-1.25,-2.375) 11(-0.75,-2.375) 12(-0.25,-2.375) 13(0.25,-2.375) 14(0.75,-2.375) 15(1.25,-2.375) 26(1.25,2.375) 27(0.75,2.375) 28(0.25,2.375) 29(-0.25,2.375) 30(-0.75,2.375) 31(-1.25,2.375)
  rect 3.251x3.251 smd: 33(0,0)
QFN65P600X600X100-29VNA
  oval 0.864x0.356 smd: 1(-2.95,1.95) 2(-2.95,1.3) 3(-2.95,0.65) 4(-2.95,0) 5(-2.95,-0.65) 6(-2.95,-1.3) 7(-2.95,-1.95) 15(2.95,-1.95) 16(2.95,-1.3) 17(2.95,-0.65) 18(2.95,0) 19(2.95,0.65) 20(2.95,1.3) 21(2.95,1.95)
  oval 0.356x0.864 smd: 8(-1.95,-2.95) 9(-1.3,-2.95) 10(-0.65,-2.95) 11(0,-2.95) 12(0.65,-2.95) 13(1.3,-2.95) 14(1.95,-2.95) 22(1.95,2.95) 23(1.3,2.95) 24(0.65,2.95) 25(0,2.95) 26(-0.65,2.95) 27(-1.3,2.95) 28(-1.95,2.95)
  rect 3.81x3.81 smd: 29(0,0)
RESC1005X37N
  rect 0.66x0.66 smd: 1(-0.44,0) 2(0.44,0)
RESC1005X40N
  rect 0.559x0.61 smd: 1(-0.48,0) 2(0.48,0)
RESC1005X50N
  rect 0.559x0.61 smd: 1(-0.48,0) 2(0.48,0)
RESC1608X50N
  rect 0.711x0.991 smd: 1(-0.69,0) 2(0.69,0)
RESC1608X55N
  rect 0.889x0.991 smd: 1(-0.838,0) 2(0.838,0)
RESC2012X70N
  rect 1.041x1.397 smd: 1(-0.95,0) 2(0.95,0)
RESC3216X70N
  rect 1.143x1.803 smd: 1(-1.45,0) 2(1.45,0)
RESCAXE50P100X200X45-8N
  rect 0.711x0.254 smd: 1(-0.55,0.75) 2(-0.55,0.25) 3(-0.55,-0.25) 4(-0.55,-0.75) 5(0.55,-0.75) 6(0.55,-0.25) 7(0.55,0.25) 8(0.55,0.75)
SAMTEC_LSS-150-01-L-DV-A-K
  round 0.508 hole 0.838 unplated: (-16.625,1.1) (16.625,1.1)
  rect 0.381x1.6 smd: 1(15.557,-1.8) 2(15.557,1.8) 3(14.922,-1.8) 4(14.922,1.8) 5(14.287,-1.8) 6(14.287,1.8) 7(13.652,-1.8) 8(13.652,1.8) 9(13.018,-1.8) 10(13.018,1.8) 11(12.383,-1.8) 12(12.383,1.8) 13(11.748,-1.8) 14(11.748,1.8) 15(11.113,-1.8) 16(11.113,1.8) 17(10.477,-1.8) 18(10.477,1.8) 19(9.842,-1.8) 20(9.842,1.8) 21(9.207,-1.8) 22(9.207,1.8) 23(8.572,-1.8) 24(8.572,1.8) 25(7.938,-1.8) 26(7.938,1.8) 27(7.303,-1.8) 28(7.303,1.8) 29(6.668,-1.8) 30(6.668,1.8) 31(6.032,-1.8) 32(6.032,1.8) 33(5.397,-1.8) 34(5.397,1.8) 35(4.763,-1.8) 36(4.763,1.8) 37(4.128,-1.8) 38(4.128,1.8) 39(3.493,-1.8) 40(3.493,1.8) 41(2.857,-1.8) 42(2.857,1.8) 43(2.223,-1.8) 44(2.223,1.8) 45(1.587,-1.8) 46(1.587,1.8) 47(0.953,-1.8) 48(0.953,1.8) 49(0.318,-1.8) 50(0.318,1.8) 51(-0.318,-1.8) 52(-0.318,1.8) 53(-0.953,-1.8) 54(-0.953,1.8) 55(-1.587,-1.8) 56(-1.587,1.8) 57(-2.223,-1.8) 58(-2.223,1.8) 59(-2.857,-1.8) 60(-2.857,1.8) 61(-3.493,-1.8) 62(-3.493,1.8) 63(-4.128,-1.8) 64(-4.128,1.8) 65(-4.763,-1.8) 66(-4.763,1.8) 67(-5.397,-1.8) 68(-5.397,1.8) 69(-6.032,-1.8) 70(-6.032,1.8) 71(-6.668,-1.8) 72(-6.668,1.8) 73(-7.303,-1.8) 74(-7.303,1.8) 75(-7.938,-1.8) 76(-7.938,1.8) 77(-8.572,-1.8) 78(-8.572,1.8) 79(-9.207,-1.8) 80(-9.207,1.8) 81(-9.842,-1.8) 82(-9.842,1.8) 83(-10.477,-1.8) 84(-10.477,1.8) 85(-11.113,-1.8) 86(-11.113,1.8) 87(-11.748,-1.8) 88(-11.748,1.8) 89(-12.383,-1.8) 90(-12.383,1.8) 91(-13.018,-1.8) 92(-13.018,1.8) 93(-13.652,-1.8) 94(-13.652,1.8) 95(-14.287,-1.8) 96(-14.287,1.8) 97(-14.922,-1.8) 98(-14.922,1.8) 99(-15.557,-1.8) 100(-15.557,1.8)
SAMTEC_SHF-105-01-L-D-TH
  rect 1.067x1.067 hole 0.737: 1(0,0)
  round 1.067 hole 0.737: 2(0,1.27) 3(1.27,0) 4(1.27,1.27) 5(2.54,0) 6(2.54,1.27) 7(3.81,0) 8(3.81,1.27) 9(5.08,0) 10(5.08,1.27)
SAMTEC_TSM-103-01-T-SV
  rect 1.27x3.429 smd: 1(2.54,-1.473) 2(0,1.473) 3(-2.54,-1.473)
SOIC127P1030X265-16N
  rect 2.007x0.61 smd: 1(-4.45,4.445) 2(-4.45,3.175) 3(-4.45,1.905) 4(-4.45,0.635) 5(-4.45,-0.635) 6(-4.45,-1.905) 7(-4.45,-3.175) 8(-4.45,-4.445) 9(4.45,-4.445) 10(4.45,-3.175) 11(4.45,-1.905) 12(4.45,-0.635) 13(4.45,0.635) 14(4.45,1.905) 15(4.45,3.175) 16(4.45,4.445)
SOP65P640X120-14N
  rect 1.524x0.457 smd: 1(-2.9,1.95) 2(-2.9,1.3) 3(-2.9,0.65) 4(-2.9,0) 5(-2.9,-0.65) 6(-2.9,-1.3) 7(-2.9,-1.95) 8(2.9,-1.95) 9(2.9,-1.3) 10(2.9,-0.65) 11(2.9,0) 12(2.9,0.65) 13(2.9,1.3) 14(2.9,1.95)
SOT65P210X110-5N
  rect 0.94x0.406 smd: 1(-1.1,0.65) 2(-1.1,0) 3(-1.1,-0.65) 4(1.1,-0.65) 5(1.1,0.65)
SOT95P280X100-5N
  rect 1.092x0.533 smd: 1(-1.35,0.95) 2(-1.35,0) 3(-1.35,-0.95) 4(1.35,-0.95) 5(1.35,0.95)
SOT95P280X145-5N
  rect 1.092x0.61 smd: 1(-1.3,0.95) 2(-1.3,0) 3(-1.3,-0.95) 4(1.3,-0.95) 5(1.3,0.95)
SOT95P280X145-6N
  rect 1.092x0.584 smd: 1(-1.3,0.95) 2(-1.3,0) 3(-1.3,-0.95) 4(1.3,-0.95) 5(1.3,0) 6(1.3,0.95)
SOT143X100N
  rect 0.889x1.194 smd: 1(-1,0.75)
  rect 0.889x0.787 smd: 2(-1,-0.95) 3(1,-0.95) 4(1,0.95)
SW_KMR223GLFG
  rect 0.889x0.991 smd: 1(-2.05,-0.8) 2(-2.05,0.8) 4(2.05,0.8) 5(2.05,-0.8)
  rect 1.702x0.559 smd: 3(0,1.425)
SW_RDTAR10S1R
  rect 2.591x1.194 smd: 1(-5.994,2.54) 2(5.994,-2.54) 4(-5.994,-2.54) 8(5.994,2.54) C(-5.994,0) C1(5.994,0)
TP_5001_DBL
  round 1.524 hole 1.016: 1(0,0)
XTAL_CSM-7XDU
  rect 5.486x2.032 smd: 1(-4.75,0) 2(4.75,0)

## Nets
1V2: C210.2 U21.21
2V7: C209.2 R17.1 R102.1 U21.23
3V: C8.1 C146.1 C147.1 C148.1 C149.1 C186.1 C187.1 C188.1 C189.1 C190.1 C219.1 LED1.A LED3.A LED6.A LED7.A LED8.A P1.1 R10.1 R11.1 R19.1 R25.1 R28.1 R40.1 R42.1 R45.1 R47.1 R48.1 R49.1 R50.1 R51.1 R53.2 R67.1 R68.1 R75.1 R76.1 R77.1 R78.1 R79.1 R80.1 R86.1 R87.1 R90.1 R91.1 R92.1 R125.1 R126.1 SW1.C TP3.1 U2.2 U4.4 U6.5 U7.5 U8.5 U11.14 U12.7 U12.10 U16.5 U17.5 U18.5 U22.4
3V3OUT_FT232RQ: C195.1 C196.1 R85.1 U10.1 U10.16
GND: C1.2 C2.2 C3.2 C4.2 C5.2 C6.2 C7.2 C8.2 C9.2 C10.2 C12.2 C13.2 C14.2 C15.2 C16.2 C17.2 C18.2 C19.2 C20.2 C21.2 C22.2 C23.2 C24.2 C25.2 C26.2 C27.2 C28.2 C29.2 C30.2 C31.2 C32.2 C34.2 C35.2 C36.2 C37.2 C38.2 C39.2 C40.2 C41.2 C42.2 C43.2 C44.2 C45.2 C46.2 C47.2 C48.2 C49.2 C50.2 C51.2 C52.2 C53.2 C54.2 C55.2 C56.2 C57.2 C58.2 C59.2 C60.2 C61.2 C62.2 C63.2 C64.2 C65.2 C66.2 C67.2 C68.2 C69.2 C70.2 C71.2 C72.2 C73.2 C74.2 C75.2 C76.2 C77.2 C78.2 C79.2 C80.2 C81.2 C82.2 C83.2 C84.2 C85.2 C86.2 C87.2 C88.2 C89.2 C90.2 C91.2 C92.2 C93.2 C94.2 C95.2 C96.2 C97.2 C98.2 C99.2 C100.2 C101.2 C102.2 C103.2 C104.2 C105.2 C106.2 C107.2 C108.2 C109.2 C110.2 C111.2 C112.2 C113.2 C114.2 C115.2 C116.2 C117.2 C118.2 C119.2 C120.2 C121.2 C122.2 C123.2 C124.2 C125.2 C126.2 C127.2 C128.2 C129.2 C130.2 C131.2 C132.2 C133.2 C134.2 C135.2 C136.2 C137.2 C138.2 C139.2 C140.2 C141.2 C142.2 C143.2 C144.2 C145.2 C146.2 C147.2 C148.2 C149.2 C150.2 C152.2 C153.2 C154.2 C155.2 C156.2 C157.2 C158.2 C159.2 C160.2 C161.2 C164.2 C165.2 C166.2 C167.1 C168.2 C169.2 C170.1 C171.1 C172.2 C173.1 C175.2 C176.2 C177.2 C179.2 C180.2 C181.2 C182.2 C183.2 C184.2 C185.1 C186.2 C187.2 C188.2 C189.2 C190.2 C191.2 C192.2 C193.2 C194.2 C195.2 C196.2 C197.2 C198.2 C199.2 C200.2 C201.2 C202.2 C203.2 C204.2 C205.2 C206.2 C207.2 C208.2 C209.1 C210.1 C211.1 C213.2 C214.2 C215.2 C216.2 C217.1 C219.2 D1.2 D1.5 D2.3 D2.8 D3.3 D5.A D6.A FER2.2 FER3.2 FER4.2 J1.1 J1.2 J1.43 J1.44 J1.45 J1.46 J1.55 J1.56 J1.87 J1.94 J2.1 J2.2 J2.24 J2.25 J2.48 J2.51 J2.62 J2.68 J2.71 J2.79 J2.80 J3.1 J3.2 J3.22 J3.25 J3.36 J3.39 J3.41 J3.46 J3.60 J3.76 J3.85 J3.90 J3.98 J3.100 P1.3 P1.5 P3.A1 P3.A12 P3.B1 P3.B12 P3.S1 P3.S2 R1.2 R4.2 R5.2 R12.2 R13.2 R15.2 R18.2 R20.2 R21.2 R22.2 R36.2 R37.2 R38.2 R39.2 R41.2 R43.2 R44.2 R54.2 R57.1 R59.2 R60.1 R71.2 R74.2 R81.2 R82.2 R88.2 R89.2 R93.2 R101.2 R103.2 R104.2 R105.2 R117.2 R118.2 R122.2 R123.2 R127.1 SW2.1 U1.A1 U1.A20 U1.B1 U1.B2 U1.B19 U1.C3 U1.C4 U1.C5 U1.C6 U1.C14 U1.C15 U1.C16 U1.C17 U1.C18 U1.D2 U1.D4 U1.D5 U1.D6 U1.D7 U1.D12 U1.D13 U1.D14 U1.D15 U1.D16 U1.D17 U1.D18 U1.E3 U1.E18 U1.F3 U1.F18 U1.G3 U1.G18 U1.H2 U1.H3 U1.H8 U1.H9 U1.H10 U1.H11 U1.H12 U1.H13 U1.H18 U1.J3 U1.J8 U1.J9 U1.J10 U1.J11 U1.J12 U1.J13 U1.J18 U1.K1 U1.K2 U1.K3 U1.K8 U1.K9 U1.K10 U1.K11 U1.K12 U1.K13 U1.K17 U1.K18 U1.K19 U1.K20 U1.L2 U1.L3 U1.L8 U1.L9 U1.L10 U1.L11 U1.L12 U1.L13 U1.L16 U1.L17 U1.M1 U1.M2 U1.M8 U1.M9 U1.M10 U1.M11 U1.M12 U1.M13 U1.M17 U1.M18 U1.N2 U1.N8 U1.N9 U1.N10 U1.N11 U1.N12 U1.N13 U1.N17 U1.N18 U1.P1 U1.P17 U1.P19 U1.P20 U1.R2 U1.R17 U1.T1 U1.T4 U1.T17 U1.U1 U1.U4 U1.U5 U1.U16 U1.U17 U1.V3 U1.V4 U1.V15 U1.V16 U1.V18 U1.W1 U1.W2 U1.W19 U1.W20 U1.Y1 U1.Y2 U1.Y5 U1.Y7 U1.Y13 U1.Y16 U1.Y19 U1.Y20 U2.10 U3.2 U4.1 U5.2 U5.5 U5.10 U5.19 U6.3 U7.3 U8.3 U9.3 U9.4 U9.6 U9.23 U9.25 U10.4 U10.17 U10.20 U10.24 U10.26 U10.33 U11.7 U12.4 U12.8 U12.11 U12.12 U12.13 U12.14 U12.15 U13.A9 U13.B1 U13.B3 U13.B9 U13.D1 U13.D8 U13.E1 U13.E2 U13.E8 U13.F9 U13.G1 U13.G8 U13.G9 U13.J2 U13.J8 U13.M1 U13.M9 U13.P1 U13.P9 U13.T1 U13.T9 U14.1 U14.4 U14.7 U14.13 U15.4 U15.13 U15.21 U16.6 U16.29 U17.3 U18.3 U21.3 U21.10 U21.22 U21.25 U22.2 U22.5
VBUS_TYPEC: C211.2 C212.1 D6.K JP1.1 R106.1 R111.1 U19.1 U19.2 U19.3 U20.1 U20.2 U20.3 U20.5 U20.6 U20.7 U20.8 U20.9 U21.24
VDD_CONNECTOR: J3.97 J3.99 JP1.3
VDD_EXT: C39.1 C40.1 C45.1 C72.1 C73.1 C74.1 C75.1 C76.1 C77.1 C78.1 C79.1 C80.1 C81.1 C82.1 C83.1 C84.1 C85.1 C86.1 C87.1 C88.1 C124.1 C125.1 C126.1 C127.1 C128.1 C129.1 C150.1 C153.1 C156.1 C157.1 C163.1 C164.1 C165.1 C166.1 C169.1 C170.2 C171.2 C172.1 C175.1 C176.1 C200.1 C217.2 L4.2 R53.1 R55.1 R62.2 R95.1 R99.1 TP4.1 U1.D8 U1.D9 U1.D10 U1.D11 U1.K4 U1.L4 U1.M4 U1.M16 U1.N4 U1.N16 U1.P4 U1.P16 U1.R4 U1.R16 U1.T5 U1.T16 U1.U6 U1.U7 U1.U8 U1.U9 U1.U10 U1.U11 U1.U12 U1.U13 U1.U14 U1.U15 U3.1 U3.3 U5.3 U5.4 U5.11 U5.12 U5.13 U5.15 U14.3 U14.8 U14.9 U14.10 U15.2
VDD_INPUT: C155.1 C158.1 C159.1 C160.1 C161.1 JP1.2 R29.1 U15.6 U15.11
VDD_INT: C41.1 C42.1 C52.1 C53.1 C54.1 C55.1 C56.1 C57.1 C58.1 C59.1 C60.1 C61.1 C62.1 C63.1 C64.1 C65.1 C66.1 C67.1 C68.1 C69.1 C70.1 C71.1 C113.1 C114.1 C115.1 C116.1 C120.1 C121.1 C122.1 C123.1 C130.1 C131.1 C152.1 C177.1 C178.1 C179.1 C180.1 C181.1 C182.1 C183.1 C184.1 C218.2 L1.1 L5.2 R61.2 R64.1 R98.1 R116.2 R120.1 U1.E4 U1.E5 U1.E6 U1.E7 U1.E8 U1.E9 U1.E10 U1.E11 U1.E12 U1.E13 U1.E14 U1.E15 U1.E16 U1.E17 U1.F4 U1.F5 U1.F16 U1.F17 U1.G4 U1.G5 U1.G16 U1.G17 U1.H4 U1.H5 U1.H16 U1.H17 U1.J5 U1.J14 U1.J15 U1.J16 U1.J17 U1.K5 U1.K14 U1.K15 U1.K16 U1.L5 U1.L14 U1.L15 U1.M5 U1.M6 U1.M14 U1.N6 U1.N7 U1.N14 U1.P6 U1.P7 U1.P8 U1.P9 U1.P10 U1.P11 U1.P12 U1.P13 U1.P14 U1.R6 U1.R7 U1.R8 U1.R9 U1.R10 U1.R11 U1.R12 U1.R13 U1.R14
VDD_PLL: C32.1 C33.1 L1.2 R119.1 U1.K6 U1.L6
VDD_VREF_EXT: C36.1 C37.1 C38.1 C43.1 C44.1 C46.1 C47.1 C48.1 C49.1 C50.1 C51.1 C132.1 C133.1 C134.1 C135.1 C136.1 C137.1 C138.1 C139.1 C140.1 C154.1 C197.1 C198.1 C199.1 R26.1 R96.1 R124.1 TP2.1 U1.G10 U1.G11 U1.M15 U1.N5 U1.N15 U1.P5 U1.P15 U1.R5 U1.R15 U1.T6 U1.T7 U1.T8 U1.T9 U1.T10 U1.T11 U1.T12 U1.T13 U1.T14 U1.T15 U3.5
1_8V: FER3.1 R14.1 R26.2 R27.1 R97.1
1_35V: C5.1 C6.1 C11.1 C21.1 C22.1 C23.1 C24.1 C25.1 C26.1 C27.1 C89.1 C90.1 C91.1 C92.1 C93.1 C94.1 C95.1 C96.1 C97.1 C98.1 C99.1 C100.1 C101.1 C102.1 C103.1 C104.1 C105.1 C106.1 C107.1 C108.1 C109.1 C110.1 C111.1 C112.1 C117.1 C118.1 C119.1 C151.1 C214.1 C215.1 C216.1 J3.92 L3.2 R3.1 R6.1 R63.1 R100.1 TP1.1 U1.F6 U1.F7 U1.F8 U1.F9 U1.F10 U1.F11 U1.F12 U1.F13 U1.F14 U1.F15 U1.G6 U1.G7 U1.G8 U1.G9 U1.G12 U1.G13 U1.G14 U1.G15 U1.H6 U1.H7 U1.H14 U1.H15 U1.J6 U1.J7 U1.K7 U12.2 U13.A1 U13.A8 U13.B2 U13.C1 U13.C9 U13.D2 U13.D9 U13.E9 U13.F1 U13.G7 U13.H2 U13.H9 U13.K2 U13.K8 U13.N1 U13.N9 U13.R1 U13.R9
AUDIO_CLK: J3.40 R24.2
CC1: D3.2 P3.A5 U21.1 U21.2
CC2: D3.1 P3.B5 U21.4 U21.5
CLK1: J3.42 R30.2
CLK2: J3.44 R31.2
DAI0_PIN01: J1.3 U1.Y8
DAI0_PIN02: J1.5 U1.V9
DAI0_PIN03: J1.7 U1.W9
DAI0_PIN04: J1.9 U1.Y9
DAI0_PIN05: J1.11 U1.W10
DAI0_PIN06: J1.13 U1.V10
DAI0_PIN07: J1.15 U1.Y10
DAI0_PIN08: J1.17 U1.W11
DAI0_PIN09: J1.19 U1.V11
DAI0_PIN10: J1.21 U1.Y11
DAI0_PIN11: J1.23 U1.Y12
DAI0_PIN12: J1.25 U1.W12
DAI0_PIN19: J1.39 U1.W13
DAI0_PIN20: J1.41 U1.V12
DAI1_PIN01: J1.4 U1.R20
DAI1_PIN02: J1.6 U1.P18
DAI1_PIN03: J1.8 U1.R18
DAI1_PIN04: J1.10 U1.T20
DAI1_PIN05: J1.12 U1.U20
DAI1_PIN06: J1.14 U1.T19
DAI1_PIN07: J1.16 U1.U19
DAI1_PIN08: J1.18 U1.R19
DAI1_PIN09: J1.20 U1.T18
DAI1_PIN10: J1.22 U1.U18
DAI1_PIN11: J1.24 U1.V19
DAI1_PIN12: J1.26 U1.V20
DAI1_PIN19: J1.40 U1.V17
DAI1_PIN20: J1.42 U1.W18
DMC0_A00: RN1.1 U1.D19 U13.N3
DMC0_A01: RN3.2 U1.D20 U13.P7
DMC0_A02: RN2.2 U1.C20 U13.P3
DMC0_A03: RN5.2 U1.C19 U13.N2
DMC0_A04: RN4.1 U1.A19 U13.P8
DMC0_A05: RN5.3 U1.B20 U13.P2
DMC0_A06: RN3.4 U1.B18 U13.R8
DMC0_A07: RN5.4 U1.A18 U13.R2
DMC0_A08: RN3.3 U1.A16 U13.T8
DMC0_A09: RN2.4 U1.B16 U13.R3
DMC0_A10: RN7.1 U1.A15 U13.L7
DMC0_A11: RN1.4 U1.B15 U13.R7
DMC0_A12: RN4.2 U1.B14 U13.N7
DMC0_A13: RN2.3 U1.A14 U13.T3
DMC0_A14: RN3.1 U1.A13 U13.T7
DMC0_A15: RN4.4 U1.B13 U13.M7
DMC0_BA0: RN5.1 U1.B17 U13.M2
DMC0_BA1: RN4.3 U1.A17 U13.N8
DMC0_BA2: RN1.2 U1.E19 U13.M3
DMC0_CK: R16.1 U1.J20 U13.J7
DMC0_CKE: RN7.2 U1.H20 U13.K9
DMC0_DQ00: U1.J2 U13.E3
DMC0_DQ01: U1.E1 U13.F7
DMC0_DQ02: U1.H1 U13.F2
DMC0_DQ03: U1.D1 U13.F8
DMC0_DQ04: U1.G2 U13.H3
DMC0_DQ05: U1.E2 U13.H8
DMC0_DQ06: U1.J1 U13.G2
DMC0_DQ07: U1.G1 U13.H7
DMC0_DQ08: U1.C2 U13.D7
DMC0_DQ09: U1.B6 U13.C3
DMC0_DQ10: U1.B5 U13.C8
DMC0_DQ11: U1.A5 U13.C2
DMC0_DQ12: U1.A2 U13.A7
DMC0_DQ13: U1.B3 U13.A2
DMC0_DQ14: U1.D3 U13.B8
DMC0_DQ15: U1.A3 U13.A3
DMC0_LDM: U1.C1 U13.E7
DMC0_LDQS: U1.F2 U13.F3
DMC0_ODT: RN6.2 U1.H19 U13.K1
DMC0_RZQ: R1.1 U1.G19
DMC0_UDM: U1.A6 U13.D3
DMC0_UDQS: U1.B4 U13.C7
DMC0_VREF: C9.1 C10.1 R2.1 R7.2 R8.2
HADC0_VIN0: J1.47 U1.N19
HADC0_VIN1: J1.49 U1.N20
HADC0_VIN2: J1.51 U1.M19
HADC0_VIN3: J1.53 U1.M20
ID0: J2.76 R126.2 U22.1
ID1: J2.78 R125.2 U22.3
INTVCC: C167.2 R56.1 R58.1 U15.3
JTG0_TCK/SWCLK: J3.50 P1.4 U1.B11
JTG0_TDI: J3.54 P1.8 U1.C13
JTG0_TDO/SWO: J3.52 P1.6 U1.C11
JTG0_TMS/SWDIO: J3.48 P1.2 U1.C12
N1: J1.92 J2.12 J2.30 J2.52 U1.C8
N2: J1.90 J2.28 J2.97 U1.B7
N3: J1.88 J2.23 J2.50 U1.C7
N4: J1.98 J2.37 J2.38 R115.2 U1.C9
N5: J1.100 J2.35 J2.36 R114.2 U1.A7
N6: J2.34 R70.1 U1.W7
N7: J2.20 U1.Y6
N8: J2.16 J2.33 U1.V8
N9: J2.10 J2.21 J2.49 U1.V2 U11.5
N10: J2.8 J2.19 J2.47 U1.U3 U11.2
N11: J2.6 J2.17 J2.45 R90.2 U1.V1 U11.12
N12: J2.4 J2.15 J2.43 R91.2 U1.T3 U11.9
N13: J2.7 U1.P2 U7.2
PA_00/SPI2_MISO/OSPI_MISO/SMC0_D00: J2.3 R72.2 U1.N3
PA_01/SPI2_MOSI/OSPI_MOSI/SMC0_D01: J2.5 U1.P3 U2.15
PA_03/SPI2_D3/OSPI_D3/TWI3_SDA/SMC0_D03: J2.9 U1.R3 U8.2
PA_04/SPI2_CLK/OSPI_CLK/SMC0_D04: J2.11 R73.1 U1.R1
PA_05/SPI2_SEL1B/OSPI_SEL1B/SMC0_D05/SPI2_SSB: J2.13 U1.T2 U6.2
PA_10/TWI0_SCL/SPI1_CLK/TM0_TMR0/SMC0_D10: J2.14 J2.31 U1.U2
PA_12/FLG0/SPI1_MOSI/TM0_TMR1/SMC0_D12: J2.18 U1.W6
PA_15/TWI2_SDA/SPI1_D3/UART1_TXB/SMC0_D15: J2.32 R69.1 U1.W8
PB_02/MLB0_CLK/FLG3/LP1_ACK/SMC0_AWEB/TM0_ACLK4: J1.96 J2.98 U1.B8
PB_06/LP0_CLK/SPI1_SEL5B/TRACE0_CLK: J2.99 U1.V5
PB_07/LP0_D0/SPI2_SEL5B/TRACE0_D00: J2.95 U1.W4
PB_08/LP0_D1/SPI1_SEL7B/TM0_TMR6/TRACE0_D01: J2.93 U1.W3
PB_09/LP0_D2/SPI2_SEL7B/TM0_TMR7/TRACE0_D02: J2.91 U1.V6
PB_10/LP0_D3/SPI1_SEL2B/TRACE0_D03: J2.22 J2.89 U1.Y3
PB_11/LP0_D4/SPI0_RDY/UART2_RXB/TM0_ACI2: J2.26 J2.42 J2.87 U1.Y4
PB_12/LP0_D5/SPI2_SEL3B/UART2_TXB: J2.40 J2.85 U1.V7
PB_13/SPI2_DQS/LP0_D6/SPI1_SEL3B/UART2_RTSB: J2.27 J2.44 J2.83 U1.W5
PB_14/LP0_D7/SPI0_SEL3B/UART2_CTSB: J2.46 J2.81 U1.Y14
PB_15/LP1_D0/SPI0_SEL4B/SMC0_ADDR4: J2.96 U1.W14
PC_00/LP1_D1/TWI4_SCL/TRACE0_D04/SPI1_SEL4B: J2.94 U1.V13
